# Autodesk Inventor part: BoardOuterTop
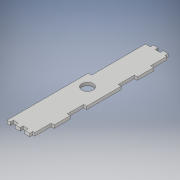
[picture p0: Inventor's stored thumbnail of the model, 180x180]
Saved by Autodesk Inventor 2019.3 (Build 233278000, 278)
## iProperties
Created: 2020-03
Part Number: BoardOuterTop
Material: Generic
Document SubType Name: Modeling
Designer: KrystynWikoff
Density: 1 g/cm^3
Appearance: Default
Author: KrystynWikoff
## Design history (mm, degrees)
sketch "Sketch1"
  geometry: L1 (0, 0)-(21.59, 0); L2 (21.59, 0)-(21.59, -107.824); L3 (21.59, -107.824)-(0, -107.824); L4 (0, -107.824)-(0, 0)
  constraints: 8 end point, 2 parallel, 1 horizontal, 1 perpendicular
  dimensions: "d0" = 107.8244 distance of L3.end L1.start; "d1" = 21.59 distance of L1.start L1.end
extrude "Extrusion1" new body sketch "Sketch1" distance "d2" = 2.3622; taper "d3" = 0 deg
sketch "Sketch2" dims "d11" = 25.4, "d22" = 25.4
  geometry: L1 (0, 0)-(-3.81, 0); L2 (-3.81, 0)-(-3.81, 2.362); L3 (-3.81, 2.362)-(0, 2.362); L4 (0, 2.362)-(0, 0); L5 (-7.62, 0)-(-11.43, 0); L6 (-11.43, 0)-(-11.43, 2.362); L7 (-11.43, 2.362)-(-7.62, 2.362); L8 (-7.62, 2.362)-(-7.62, 0); L9 (-15.24, 0)-(-19.05, 0); L10 (-19.05, 0)-(-19.05, 2.362); L11 (-19.05, 2.362)-(-15.24, 2.362); L12 (-15.24, 2.362)-(-15.24, 0); L13 (0, 107.824)-(-3.81, 107.824); L14 (-3.81, 107.824)-(-3.81, 105.462); L15 (-3.81, 105.462)-(0, 105.462); L16 (0, 105.462)-(0, 107.824); L17 (0, 107.824)-(-21.59, 107.824) reference; L18 (0, 0)-(0, 107.824) reference; L19 (-11.43, 105.462)-(-7.62, 105.462); L20 (-11.43, 107.824)-(-11.43, 105.462); L21 (-7.62, 105.462)-(-7.62, 107.824); L22 (-7.62, 107.824)-(-11.43, 107.824); L23 (-19.05, 105.462)-(-15.24, 105.462); L24 (-19.05, 107.824)-(-19.05, 105.462); L25 (-15.24, 105.462)-(-15.24, 107.824); L26 (-15.24, 107.824)-(-19.05, 107.824)
  constraints: 48 end point, 4 horizontal, 4 parallel, 2 perpendicular, 1 collinear, 31 other
  dimensions: "d4" = 3.81 distance of L2.end L3.end; "d5" = 2.3622 distance of L3.end L1.start; "d8" = 7.62 distance of L2.end L6.end; "d13" = 3.81 distance of L14.end L15.end; "d14" = 2.3622 distance of L13.end L14.end; "d15" = 0 distance between parallel lines of L17 L13; "d16" = 0 distance between parallel lines of L18 L16; "d19" = 7.62 distance of L15.end L19.end
extrude "Extrusion2" cut sketch "Sketch2" distance "d24" = 2.3622; taper "d25" = 0 deg
sketch "Sketch3" dims "d33" = 25.4, "d42" = 25.4
  geometry: L1 (0, 105.462)-(0, 2.362) reference; L2 (0, 2.362)-(-2.362, 2.362); L3 (-2.362, 2.362)-(-2.362, 15.062); L4 (-2.362, 15.062)-(0, 15.062); L5 (0, 15.062)-(0, 2.362); L6 (0, 27.762)-(-2.362, 27.762); L7 (-2.362, 27.762)-(-2.362, 40.462); L8 (-2.362, 40.462)-(0, 40.462); L9 (0, 40.462)-(0, 27.762); L10 (0, 105.462)-(-2.362, 105.462); L11 (-2.362, 105.462)-(-2.362, 92.762); L12 (-2.362, 92.762)-(0, 92.762); L13 (0, 92.762)-(0, 105.462); L14 (0, 80.062)-(-2.362, 80.062); L15 (-2.362, 80.062)-(-2.362, 67.362); L16 (-2.362, 67.362)-(0, 67.362); L17 (0, 67.362)-(0, 80.062); 1 further point
  constraints: 32 end point, 4 parallel, 2 horizontal, 2 perpendicular, 2 vertical, 16 other
  dimensions: "d26" = 12.7 distance of L2.end L3.end; "d27" = 2.3622 distance of L3.end L4.end; "d30" = 25.4 distance of L3.end L7.end; "d35" = 12.7 distance of L10.end L11.end; "d36" = 2.3622 distance of L11.end L12.end; "d39" = 25.4 distance of L11.end L15.end
extrude "Extrusion3" cut sketch "Sketch3" distance "d44" = 2.3622; taper "d45" = 0 deg
sketch "Sketch4"
  geometry: L1 (-21.59, 0)-(-21.59, 107.824) reference; L2 (-21.59, 107.824)-(-19.05, 107.824); L3 (-19.05, 107.824)-(-19.05, 63.374); L4 (-19.05, 63.374)-(-21.59, 63.374); L5 (-21.59, 63.374)-(-21.59, 107.824); 1 further point
  constraints: 8 end point, 2 parallel, 1 horizontal, 1 perpendicular
  dimensions: "d46" = 2.54 distance of L3.end L4.end; "d47" = 44.45 distance of L2.end L3.end
extrude "Extrusion4" cut sketch "Sketch4" distance "d48" = 25.4; taper "d49" = 0 deg
sketch "Sketch5"
  geometry: L1 (0, 40.462)-(0, 67.362) reference; L2 (-15.24, 0)-(-11.43, 0) reference; C1 r 4.445 at (-12.7, 53.912); 1 further point
  constraints: 1 centre point
  dimensions: "d50" = 8.89 diameter of C1; "d51" = 12.7 distance from line of L1 C1.centre; "d52" = 53.9115 distance from line of C1.centre L2
extrude "Extrusion5" cut sketch "Sketch5" distance "d53" = 25.4; taper "d54" = 0 deg
body "Solid1"
